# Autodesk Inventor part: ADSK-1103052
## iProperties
Shininess: 50.0
Length Units: 11272
Angle Units: 11279
Time Units: 11290
Mass Units: 11286
Length Display Precision: 4
Angle Display Precision: 2
Compacted: True
Created: 2000-08
Part Number: ADSK-1103052
Document SubType Name: Modeling
Description: LINK
Mass: 0.11842 g
Surface Area: 0.894828 cm^2
Volume: 0.0436976 cm^3
Density: 2.71 g/cm^3
Material: Aluminum-6061
Density: 0.0
Volumn: 0.0
Area: 0.0
PropertySet Name: Model Information
Control State: 0
Master: False
Checked Out: False
Author: Autodesk, Inc.
